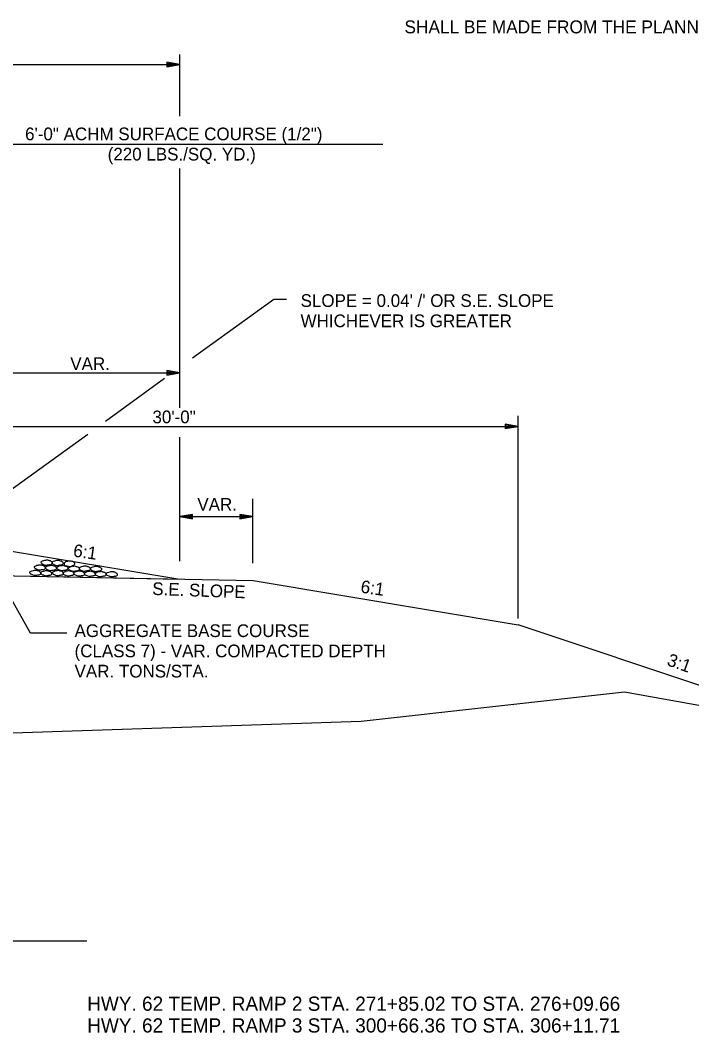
# Model space of a CAD drawing. Extents: x 1734743 to 1735935, y 759845 to 763831.
# Drawn here: x 1735771.91 to 1735803.12, y 759847.49 to 759894.55 of the extents above; entities that cross this region are included whole.
import ezdxf

# ---------------------------------------------------------------- set-up
doc = ezdxf.new("R2010")
doc.units = 0
for name, color, linetype in [('1', 7, 'Continuous'), ('19', 7, 'Continuous'), ('Level 1', 7, 'Continuous')]:
    doc.layers.add(name, color=color, linetype=linetype)

# ---------------------------------------------------------------- blocks, each defined once
blk = doc.blocks.new('ROCKS')
at = {"layer": '1'}
blk.add_spline([(0.013, 0.06), (0.053, 0.053), (0.107, 0.033), (0.133, 0.013), (0.133, -0.007), (0.12, -0.033), (0.107, -0.04), (0.073, -0.053), (0.033, -0.067), (0.013, -0.067), (-0.02, -0.06), (-0.06, -0.053), (-0.087, -0.047), (-0.113, -0.02), (-0.113, -0.007), (-0.107, 0.02), (-0.087, 0.033), (-0.067, 0.047), (-0.033, 0.053), (-0.02, 0.06), (0.013, 0.06)], degree=3, dxfattribs=at)

msp = doc.modelspace()

# ---------------------------------------------------------------- linework, layer by layer
at = {"layer": '19'}
for p, q in [((1735779.32, 759890.098), (1735779.32, 759892.956)), ((1735735.858, 759892.494), (1735779.32, 759892.494)), ((1735778.72, 759892.599), (1735778.72, 759892.389)), ((1735779.32, 759892.494), (1735778.72, 759892.599)), ((1735779.16, 759892.509), (1735778.72, 759892.544)), ((1735778.72, 759892.389), (1735779.32, 759892.494)), ((1735778.72, 759892.439), (1735779.16, 759892.479)), ((1735765.046, 759888.799), (1735788.756, 759888.799)), ((1735779.32, 759876.543), (1735779.321, 759887.659)), ((1735779.32, 759878.162), (1735779.32, 759887.614)), ((1735779.92, 759878.853), (1735783.691, 759881.589)), ((1735783.691, 759881.589), (1735784.284, 759881.589)), ((1735778.72, 759878.27), (1735778.72, 759878.06)), ((1735779.32, 759878.165), (1735778.72, 759878.27)), ((1735779.16, 759878.18), (1735778.72, 759878.215)), ((1735771.046, 759878.165), (1735779.32, 759878.165)), ((1735775.878, 759875.92), (1735778.618, 759877.908)), ((1735778.72, 759878.06), (1735779.32, 759878.165)), ((1735778.72, 759878.11), (1735779.16, 759878.15)), ((1735795.046, 759866.75), (1735795.046, 759876.17)), ((1735765.046, 759875.675), (1735795.046, 759875.675)), ((1735794.446, 759875.78), (1735794.446, 759875.57)), ((1735795.046, 759875.675), (1735794.446, 759875.78)), ((1735794.886, 759875.69), (1735794.446, 759875.725)), ((1735794.446, 759875.57), (1735795.046, 759875.675)), ((1735794.446, 759875.62), (1735794.886, 759875.66)), ((1735771.434, 759872.696), (1735775.048, 759875.318)), ((1735779.32, 759869.416), (1735779.32, 759875.17)), ((1735782.722, 759869.314), (1735782.722, 759872.312)), ((1735779.92, 759871.585), (1735779.32, 759871.48)), ((1735779.92, 759871.375), (1735779.92, 759871.585)), ((1735782.122, 759871.585), (1735782.122, 759871.375)), ((1735782.722, 759871.48), (1735782.122, 759871.585)), ((1735779.32, 759871.48), (1735782.722, 759871.48)), ((1735779.32, 759871.48), (1735779.92, 759871.375)), ((1735779.92, 759871.53), (1735779.48, 759871.495)), ((1735779.48, 759871.465), (1735779.92, 759871.425)), ((1735782.562, 759871.495), (1735782.122, 759871.53)), ((1735782.122, 759871.375), (1735782.722, 759871.48)), ((1735782.122, 759871.425), (1735782.562, 759871.465)), ((1735771.046, 759869.952), (1735779.32, 759868.572)), ((1735772.392, 759866.063), (1735770.479, 759869.455)), ((1735767.046, 759868.819), (1735779.32, 759868.572)), ((1735767.056, 759868.819), (1735782.729, 759868.504)), ((1735782.729, 759868.504), (1735795.046, 759866.45)), ((1735809.505, 759861.629), (1735795.046, 759866.45)), ((1735774.075, 759866.062), (1735772.392, 759866.063)), ((1735743.575, 759851.763), (1735774.998, 759851.761))]:
    msp.add_line(p, q, dxfattribs=at)
msp.add_lwpolyline([(1735738.102, 759862.335), (1735746.995, 759862.994), (1735752.775, 759860.273), (1735767.375, 759861.292), (1735787.755, 759861.971), (1735799.985, 759863.33), (1735809.495, 759861.629), (1735820.81, 759864.066), (1735822.413, 759863.755)], dxfattribs=at)

# ---------------------------------------------------------------- block references
at = {"layer": 'Level 1'}
for p, xscale, yscale, rotation in [((1735772.845, 759869.12), 2.011654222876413, -2.011654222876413, 178.17361855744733), ((1735773.157, 759869.345), 2.011654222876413, -2.011654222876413, 178.17361855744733), ((1735773.362, 759869.096), 2.011654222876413, -2.011654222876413, 178.17361855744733), ((1735773.671, 759869.331), 2.011654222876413, -2.011654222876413, 178.17361855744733), ((1735773.891, 759869.093), 2.011654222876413, -2.011654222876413, 178.17361855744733), ((1735774.176, 759869.293), 2.0116542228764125, 2.0116542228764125, 0.9122903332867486), ((1735772.629, 759868.871), 2.011654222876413, -2.011654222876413, 178.17361855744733), ((1735773.143, 759868.852), 2.011654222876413, -2.011654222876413, 178.17361855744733), ((1735773.682, 759868.862), 2.011654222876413, -2.011654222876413, 178.17361855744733), ((1735774.173, 759868.846), 2.011654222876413, -2.011654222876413, 178.17361855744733), ((1735774.427, 759869.061), 2.011654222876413, -2.011654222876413, 178.17361855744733), ((1735774.669, 759868.839), 2.011654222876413, -2.011654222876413, 178.17361855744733), ((1735774.933, 759869.068), 2.011654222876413, -2.011654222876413, 178.17361855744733), ((1735775.165, 759868.828), 2.011654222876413, -2.011654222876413, 178.17361855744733), ((1735775.454, 759869.053), 2.011654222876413, -2.011654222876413, 178.17361855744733), ((1735775.665, 759868.814), 2.011654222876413, -2.011654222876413, 178.17361855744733), ((1735776.186, 759868.808), 2.011654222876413, -2.011654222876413, 178.17361855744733)]:
    msp.add_blockref('ROCKS', p, dxfattribs=dict(at, xscale=xscale, yscale=yscale, rotation=rotation))

# ---------------------------------------------------------------- texts
at = {"layer": '1'}
msp.add_text('SHALL BE MADE FROM THE PLANNED SLOPES WITHOUT THE APPROVAL OF THE ENGINEER.', height=0.6, dxfattribs=at).set_placement((1735789.766, 759893.945))
at = {"layer": '19'}
for s, height, rotation, p in [('6\'-0" ACHM SURFACE COURSE (1/2")', 0.59001, 359.9954, (1735772.136, 759888.975)), ('(220 LBS./SQ. YD.)', 0.59001, 359.9954, (1735775.973, 759888.034)), ("SLOPE = 0.04' /' OR S.E. SLOPE", 0.59001, 360, (1735784.939, 759881.226)), ('WHICHEVER IS GREATER', 0.59001, 360, (1735784.939, 759880.286)), ('VAR.', 0.59, 359.9954, (1735774.236, 759878.292)), ('30\'-0"', 0.59, 359.9954, (1735778.055, 759875.819)), ('VAR.', 0.59, 359.9954, (1735780.141, 759871.753)), ('6:1', 0.59, 351.855, (1735774.345, 759869.626)), ('S.E. SLOPE', 0.59, 357.8898, (1735778.037, 759867.841)), ('6:1', 0.59, 351.855, (1735787.703, 759867.948)), ('AGGREGATE BASE COURSE', 0.59001, 360, (1735774.435, 759865.881)), ('(CLASS 7) - VAR. COMPACTED DEPTH', 0.59001, 360, (1735774.435, 759864.941)), ('3:1', 0.59, 340.4896, (1735801.927, 759864.581)), ('VAR. TONS/STA.', 0.59001, 360, (1735774.435, 759864.001)), ('HWY. 62 TEMP. RAMP 2 STA. 271+85.02 TO STA. 276+09.66', 0.65999, 359.9954, (1735775.021, 759848.507)), ('HWY. 62 TEMP. RAMP 3 STA. 300+66.36 TO STA. 306+11.71', 0.65999, 359.9954, (1735775.021, 759847.497))]:
    msp.add_text(s, height=height, rotation=rotation, dxfattribs=at).set_placement(p)

doc.saveas('drawing.dxf')
